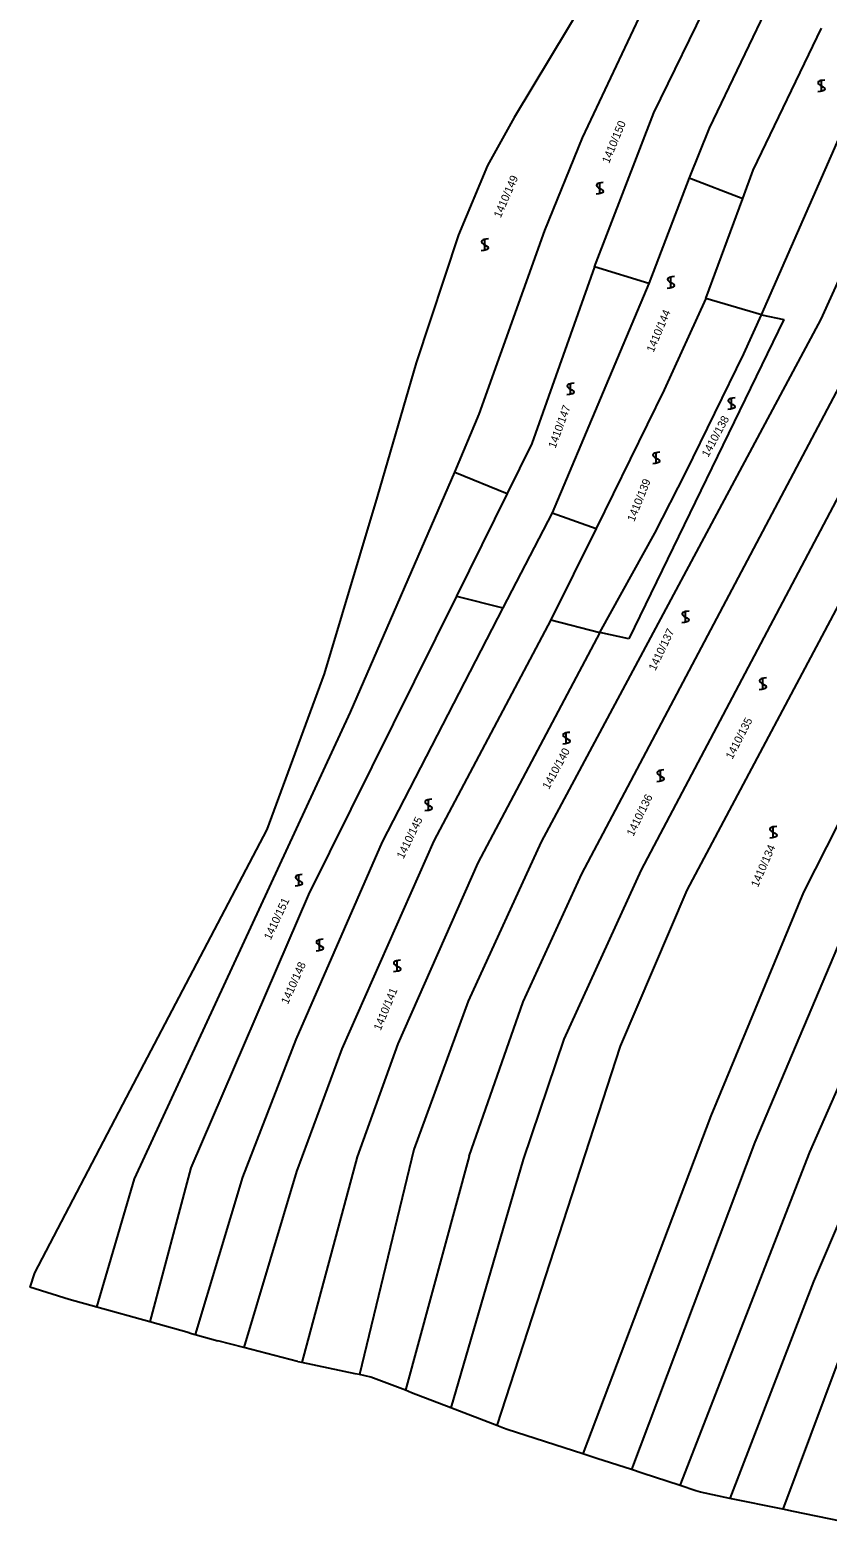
# Model space of a CAD drawing. Extents: x -580630 to -576196, y -1189024 to -1183567.
# Drawn here: x -579117.6 to -578948.4, y -1187161.3 to -1186844.5 of the extents above; entities that cross this region are included whole.
import ezdxf

# ---------------------------------------------------------------- set-up
doc = ezdxf.new("R2010")
doc.units = 0
for name, color, linetype in [('Vrstva 13', 7, 'Continuous'), ('Vrstva 18', 7, 'Continuous'), ('Vrstva 25', 7, 'Continuous'), ('Vrstva 6', 7, 'Continuous')]:
    doc.layers.add(name, color=color, linetype=linetype)

msp = doc.modelspace()

# ---------------------------------------------------------------- linework, layer by layer
at = {"layer": 'Vrstva 13'}
for p, q in [((-578999.57, -1186837.84), (-579014.8, -1186863.14)), ((-579014.8, -1186863.14), (-579020.47, -1186873.37)), ((-579020.47, -1186873.37), (-579026.64, -1186888.11)), ((-579026.64, -1186888.11), (-579035.63, -1186915.28)), ((-579035.63, -1186915.28), (-579043.9, -1186943.73)), ((-579043.9, -1186943.73), (-579055.1, -1186981.32)), ((-579055.1, -1186981.32), (-579067.33, -1187014.41)), ((-579067.33, -1187014.41), (-579097.19, -1187071.31)), ((-579097.19, -1187071.31), (-579116.64, -1187108.52)), ((-579116.64, -1187108.52), (-579117.61, -1187111.58)), ((-579109.23, -1187114.22), (-579117.61, -1187111.58)), ((-579103.42, -1187115.83), (-579109.23, -1187114.22)), ((-579092.16, -1187118.95), (-579103.42, -1187115.83)), ((-579083.76, -1187121.27), (-579092.16, -1187118.95)), ((-579083.76, -1187121.27), (-579082.53, -1187121.61)), ((-579082.53, -1187121.61), (-579077.71, -1187122.95)), ((-579072.17, -1187124.4), (-579077.71, -1187122.95)), ((-579060.76, -1187127.39), (-579072.17, -1187124.4)), ((-579060.69, -1187127.41), (-579060.76, -1187127.39)), ((-579059.87, -1187127.58), (-579060.69, -1187127.41)), ((-579048.57, -1187129.95), (-579059.87, -1187127.58)), ((-579047.64, -1187130.15), (-579048.57, -1187129.95)), ((-579045.2, -1187130.66), (-579047.64, -1187130.15)), ((-579037.89, -1187133.48), (-579045.2, -1187130.66)), ((-579036.59, -1187133.98), (-579037.89, -1187133.48)), ((-579028.28, -1187137.18), (-579036.59, -1187133.98)), ((-579018.49, -1187140.95), (-579028.28, -1187137.18)), ((-579017.04, -1187141.51), (-579018.49, -1187140.95)), ((-579016.29, -1187141.8), (-579017.04, -1187141.51)), ((-579000.21, -1187147), (-579016.29, -1187141.8)), ((-578997.23, -1187147.96), (-579000.21, -1187147)), ((-578989.87, -1187150.33), (-578997.23, -1187147.96)), ((-578987.64, -1187151.05), (-578989.87, -1187150.33)), ((-578979.56, -1187153.72), (-578987.64, -1187151.05)), ((-578976.27, -1187154.8), (-578979.56, -1187153.72)), ((-578975.26, -1187155.13), (-578976.27, -1187154.8)), ((-578969.01, -1187156.42), (-578975.26, -1187155.13)), ((-578957.79, -1187158.73), (-578969.01, -1187156.42)), ((-578955.52, -1187159.2), (-578957.79, -1187158.73)), ((-578945.5, -1187161.27), (-578955.52, -1187159.2))]:
    msp.add_line(p, q, dxfattribs=at)
at = {"layer": 'Vrstva 25'}
for points in [[(-578948.84, -1186855.22), (-578949.35, -1186855.28), (-578949.7, -1186855.33), (-578949.94, -1186855.41), (-578950.12, -1186855.52), (-578950.24, -1186855.61), (-578950.29, -1186855.78), (-578950.24, -1186856.01), (-578949.85, -1186856.33), (-578949.29, -1186856.64), (-578948.94, -1186856.91), (-578948.87, -1186857.11), (-578948.94, -1186857.31), (-578949.1, -1186857.44), (-578949.29, -1186857.51), (-578949.82, -1186857.64), (-578950.34, -1186857.71)], [(-578949.59, -1186857.72), (-578949.59, -1186856.45), (-578949.59, -1186855.22)], [(-578995.88, -1186876.98), (-578996.39, -1186877.04), (-578996.74, -1186877.09), (-578996.98, -1186877.17), (-578997.16, -1186877.28), (-578997.28, -1186877.37), (-578997.33, -1186877.54), (-578997.28, -1186877.77), (-578996.89, -1186878.09), (-578996.33, -1186878.4), (-578995.98, -1186878.67), (-578995.91, -1186878.87), (-578995.98, -1186879.07), (-578996.14, -1186879.2), (-578996.33, -1186879.27), (-578996.86, -1186879.4), (-578997.38, -1186879.47)], [(-578996.63, -1186879.48), (-578996.63, -1186878.21), (-578996.63, -1186876.98)], [(-579020.28, -1186888.97), (-579020.79, -1186889.03), (-579021.14, -1186889.08), (-579021.38, -1186889.16), (-579021.56, -1186889.27), (-579021.68, -1186889.36), (-579021.73, -1186889.53), (-579021.68, -1186889.76), (-579021.29, -1186890.08), (-579020.73, -1186890.39), (-579020.38, -1186890.66), (-579020.31, -1186890.86), (-579020.38, -1186891.06), (-579020.54, -1186891.19), (-579020.73, -1186891.26), (-579021.26, -1186891.39), (-579021.78, -1186891.46)], [(-579021.03, -1186891.47), (-579021.03, -1186890.2), (-579021.03, -1186888.97)], [(-578980.79, -1186896.96), (-578981.3, -1186897.02), (-578981.65, -1186897.07), (-578981.89, -1186897.15), (-578982.07, -1186897.26), (-578982.19, -1186897.35), (-578982.24, -1186897.52), (-578982.19, -1186897.75), (-578981.8, -1186898.07), (-578981.24, -1186898.38), (-578980.89, -1186898.65), (-578980.82, -1186898.85), (-578980.89, -1186899.05), (-578981.05, -1186899.18), (-578981.24, -1186899.25), (-578981.77, -1186899.38), (-578982.29, -1186899.45)], [(-578981.54, -1186899.46), (-578981.54, -1186898.19), (-578981.54, -1186896.96)], [(-579002.09, -1186919.6), (-579002.6, -1186919.66), (-579002.95, -1186919.71), (-579003.19, -1186919.79), (-579003.37, -1186919.9), (-579003.49, -1186919.99), (-579003.54, -1186920.16), (-579003.49, -1186920.39), (-579003.1, -1186920.71), (-579002.54, -1186921.02), (-579002.19, -1186921.29), (-579002.12, -1186921.49), (-579002.19, -1186921.69), (-579002.35, -1186921.82), (-579002.54, -1186921.89), (-579003.07, -1186922.02), (-579003.59, -1186922.09)], [(-579002.84, -1186922.1), (-579002.84, -1186920.83), (-579002.84, -1186919.6)], [(-578967.92, -1186922.71), (-578968.43, -1186922.77), (-578968.78, -1186922.82), (-578969.02, -1186922.9), (-578969.2, -1186923.01), (-578969.32, -1186923.1), (-578969.37, -1186923.27), (-578969.32, -1186923.5), (-578968.93, -1186923.82), (-578968.37, -1186924.13), (-578968.02, -1186924.4), (-578967.95, -1186924.6), (-578968.02, -1186924.8), (-578968.18, -1186924.93), (-578968.37, -1186925), (-578968.9, -1186925.13), (-578969.42, -1186925.2)], [(-578968.67, -1186925.21), (-578968.67, -1186923.94), (-578968.67, -1186922.71)], [(-578983.9, -1186934.25), (-578984.41, -1186934.31), (-578984.76, -1186934.36), (-578985, -1186934.44), (-578985.18, -1186934.55), (-578985.3, -1186934.64), (-578985.35, -1186934.81), (-578985.3, -1186935.04), (-578984.91, -1186935.36), (-578984.35, -1186935.67), (-578984, -1186935.94), (-578983.93, -1186936.14), (-578984, -1186936.34), (-578984.16, -1186936.47), (-578984.35, -1186936.54), (-578984.88, -1186936.67), (-578985.4, -1186936.74)], [(-578984.65, -1186936.75), (-578984.65, -1186935.48), (-578984.65, -1186934.25)], [(-578977.68, -1186968), (-578978.19, -1186968.06), (-578978.54, -1186968.11), (-578978.78, -1186968.19), (-578978.96, -1186968.3), (-578979.08, -1186968.39), (-578979.13, -1186968.56), (-578979.08, -1186968.79), (-578978.69, -1186969.11), (-578978.13, -1186969.42), (-578977.78, -1186969.69), (-578977.71, -1186969.89), (-578977.78, -1186970.09), (-578977.94, -1186970.22), (-578978.13, -1186970.29), (-578978.66, -1186970.42), (-578979.18, -1186970.49)], [(-578978.43, -1186970.5), (-578978.43, -1186969.23), (-578978.43, -1186968)], [(-578961.27, -1186982.2), (-578961.78, -1186982.26), (-578962.13, -1186982.31), (-578962.37, -1186982.39), (-578962.55, -1186982.5), (-578962.67, -1186982.59), (-578962.72, -1186982.76), (-578962.67, -1186982.99), (-578962.28, -1186983.31), (-578961.72, -1186983.62), (-578961.37, -1186983.89), (-578961.3, -1186984.09), (-578961.37, -1186984.29), (-578961.53, -1186984.42), (-578961.72, -1186984.49), (-578962.25, -1186984.62), (-578962.77, -1186984.69)], [(-578962.02, -1186984.7), (-578962.02, -1186983.43), (-578962.02, -1186982.2)], [(-579002.98, -1186993.75), (-579003.49, -1186993.81), (-579003.84, -1186993.86), (-579004.08, -1186993.94), (-579004.26, -1186994.05), (-579004.38, -1186994.14), (-579004.43, -1186994.31), (-579004.38, -1186994.54), (-579003.99, -1186994.86), (-579003.43, -1186995.17), (-579003.08, -1186995.44), (-579003.01, -1186995.64), (-579003.08, -1186995.84), (-579003.24, -1186995.97), (-579003.43, -1186996.04), (-579003.96, -1186996.17), (-579004.48, -1186996.24)], [(-579003.73, -1186996.25), (-579003.73, -1186994.98), (-579003.73, -1186993.75)], [(-578983.01, -1187001.74), (-578983.52, -1187001.8), (-578983.87, -1187001.85), (-578984.11, -1187001.93), (-578984.29, -1187002.04), (-578984.41, -1187002.13), (-578984.46, -1187002.3), (-578984.41, -1187002.53), (-578984.02, -1187002.85), (-578983.46, -1187003.16), (-578983.11, -1187003.43), (-578983.04, -1187003.63), (-578983.11, -1187003.83), (-578983.27, -1187003.96), (-578983.46, -1187004.03), (-578983.99, -1187004.16), (-578984.51, -1187004.23)], [(-578983.76, -1187004.24), (-578983.76, -1187002.97), (-578983.76, -1187001.74)], [(-579032.27, -1187007.95), (-579032.78, -1187008.01), (-579033.13, -1187008.06), (-579033.37, -1187008.14), (-579033.55, -1187008.25), (-579033.67, -1187008.34), (-579033.72, -1187008.51), (-579033.67, -1187008.74), (-579033.28, -1187009.06), (-579032.72, -1187009.37), (-579032.37, -1187009.64), (-579032.3, -1187009.84), (-579032.37, -1187010.04), (-579032.53, -1187010.17), (-579032.72, -1187010.24), (-579033.25, -1187010.37), (-579033.77, -1187010.44)], [(-579033.02, -1187010.45), (-579033.02, -1187009.18), (-579033.02, -1187007.95)], [(-578959.05, -1187013.73), (-578959.56, -1187013.79), (-578959.91, -1187013.84), (-578960.15, -1187013.92), (-578960.33, -1187014.03), (-578960.45, -1187014.12), (-578960.5, -1187014.29), (-578960.45, -1187014.52), (-578960.06, -1187014.84), (-578959.5, -1187015.15), (-578959.15, -1187015.42), (-578959.08, -1187015.62), (-578959.15, -1187015.82), (-578959.31, -1187015.95), (-578959.5, -1187016.02), (-578960.03, -1187016.15), (-578960.55, -1187016.22)], [(-578959.8, -1187016.23), (-578959.8, -1187014.96), (-578959.8, -1187013.73)], [(-579059.78, -1187023.94), (-579060.29, -1187024), (-579060.64, -1187024.05), (-579060.88, -1187024.13), (-579061.06, -1187024.24), (-579061.18, -1187024.33), (-579061.23, -1187024.5), (-579061.18, -1187024.73), (-579060.79, -1187025.05), (-579060.23, -1187025.36), (-579059.88, -1187025.63), (-579059.81, -1187025.83), (-579059.88, -1187026.03), (-579060.04, -1187026.16), (-579060.23, -1187026.23), (-579060.76, -1187026.36), (-579061.28, -1187026.43)], [(-579060.53, -1187026.44), (-579060.53, -1187025.17), (-579060.53, -1187023.94)], [(-579055.34, -1187037.7), (-579055.85, -1187037.76), (-579056.2, -1187037.81), (-579056.44, -1187037.89), (-579056.62, -1187038), (-579056.74, -1187038.09), (-579056.79, -1187038.26), (-579056.74, -1187038.49), (-579056.35, -1187038.81), (-579055.79, -1187039.12), (-579055.44, -1187039.39), (-579055.37, -1187039.59), (-579055.44, -1187039.79), (-579055.6, -1187039.92), (-579055.79, -1187039.99), (-579056.32, -1187040.12), (-579056.84, -1187040.19)], [(-579056.09, -1187040.2), (-579056.09, -1187038.93), (-579056.09, -1187037.7)], [(-579038.92, -1187042.14), (-579039.43, -1187042.2), (-579039.78, -1187042.25), (-579040.02, -1187042.33), (-579040.2, -1187042.44), (-579040.32, -1187042.53), (-579040.37, -1187042.7), (-579040.32, -1187042.93), (-579039.93, -1187043.25), (-579039.37, -1187043.56), (-579039.02, -1187043.83), (-579038.95, -1187044.03), (-579039.02, -1187044.23), (-579039.18, -1187044.36), (-579039.37, -1187044.43), (-579039.9, -1187044.56), (-579040.42, -1187044.63)], [(-579039.67, -1187044.64), (-579039.67, -1187043.37), (-579039.67, -1187042.14)]]:
    msp.add_lwpolyline(points, dxfattribs=at)
at = {"layer": 'Vrstva 6'}
for p, q in [((-578985.14, -1186862.19), (-578963.45, -1186817.75)), ((-578875.7, -1186834.25), (-578978.18, -1187027.28)), ((-578958.69, -1186834.68), (-578973.44, -1186865.4)), ((-579000.29, -1186867.51), (-578987.07, -1186839.43)), ((-578964.05, -1186874.33), (-578949.6, -1186844.17)), ((-578925.2, -1186851.92), (-578949.74, -1186905.97)), ((-578962.33, -1186905.11), (-578940.96, -1186856.38)), ((-578997.74, -1186894.91), (-578985.14, -1186862.19)), ((-578973.44, -1186865.4), (-578977.63, -1186876)), ((-579008.26, -1186887.2), (-579000.29, -1186867.51)), ((-578977.63, -1186876), (-578986.2, -1186898.43)), ((-578977.63, -1186876), (-578966.28, -1186880.38)), ((-578966.28, -1186880.38), (-578964.05, -1186874.33)), ((-578974.1, -1186901.62), (-578966.28, -1186880.38)), ((-579022.21, -1186926.14), (-579008.26, -1186887.2)), ((-578997.74, -1186894.91), (-579011.06, -1186932.42)), ((-578986.2, -1186898.43), (-578997.74, -1186894.91)), ((-578986.2, -1186898.43), (-579006.77, -1186947.1)), ((-578974.1, -1186901.62), (-578982.98, -1186920.97)), ((-578962.33, -1186905.11), (-578974.1, -1186901.62)), ((-578949.74, -1186905.97), (-579009.08, -1187017.03)), ((-579000.42, -1187023.78), (-578938.51, -1186906.52)), ((-578957.55, -1186906.06), (-578990.46, -1186973.9)), ((-578966.08, -1186913.39), (-578962.33, -1186905.11)), ((-578962.33, -1186905.11), (-578957.55, -1186906.06)), ((-578978.35, -1186938.59), (-578966.08, -1186913.39)), ((-578931.17, -1186915.46), (-578987.86, -1187022.91)), ((-578982.98, -1186920.97), (-578997.4, -1186950.47)), ((-579027.37, -1186938.49), (-579022.21, -1186926.14)), ((-579011.06, -1186932.42), (-579016.27, -1186943)), ((-579049.54, -1186989.43), (-579027.37, -1186938.49)), ((-579027.37, -1186938.49), (-579016.27, -1186943)), ((-578984.96, -1186951.42), (-578978.35, -1186938.59)), ((-579016.27, -1186943), (-579027.01, -1186964.81)), ((-579006.77, -1186947.1), (-579017.22, -1186967.28)), ((-579006.77, -1186947.1), (-578997.4, -1186950.47)), ((-578997.4, -1186950.47), (-579007.05, -1186969.86)), ((-578996.59, -1186972.55), (-578984.96, -1186951.42)), ((-579027.01, -1186964.81), (-579058.44, -1187028.21)), ((-579027.01, -1186964.81), (-579017.22, -1186967.28)), ((-579017.22, -1186967.28), (-579042.8, -1187016.99)), ((-579007.05, -1186969.86), (-579031.84, -1187016.76)), ((-579007.05, -1186969.86), (-578996.59, -1186972.55)), ((-578996.59, -1186972.55), (-579022.51, -1187021.49)), ((-578990.46, -1186973.9), (-578996.59, -1186972.55)), ((-578926.31, -1186974.11), (-578953.39, -1187027.68)), ((-579095.38, -1187088.59), (-579049.54, -1186989.43)), ((-578952.07, -1187082.93), (-578922.28, -1187015.01)), ((-579042.8, -1187016.99), (-579061.13, -1187058.96)), ((-579031.84, -1187016.76), (-579051.38, -1187060.97)), ((-579009.08, -1187017.03), (-579024.54, -1187050.82)), ((-579022.51, -1187021.49), (-579039.49, -1187059.87)), ((-579012.9, -1187050.98), (-579000.42, -1187023.78)), ((-578987.86, -1187022.91), (-579004.28, -1187058.94)), ((-579058.44, -1187028.21), (-579083.41, -1187086.21)), ((-578978.18, -1187027.28), (-578992.29, -1187060.38)), ((-578953.39, -1187027.68), (-578973.07, -1187075.19)), ((-578943.03, -1187031.9), (-578963.69, -1187080.78)), ((-579024.54, -1187050.82), (-579036.09, -1187082.32)), ((-579024.39, -1187083.74), (-579012.9, -1187050.98)), ((-579061.13, -1187058.96), (-579072.46, -1187088.24)), ((-579039.49, -1187059.87), (-579048.11, -1187083.89)), ((-579004.28, -1187058.94), (-579012.9, -1187084.46)), ((-579051.38, -1187060.97), (-579061.03, -1187086.99)), ((-578992.29, -1187060.38), (-579018.49, -1187140.95)), ((-578973.07, -1187075.19), (-579000.21, -1187147)), ((-579036.09, -1187082.32), (-579047.64, -1187130.15)), ((-578963.69, -1187080.78), (-578989.87, -1187150.33)), ((-579048.11, -1187083.89), (-579059.87, -1187127.58)), ((-579024.39, -1187083.74), (-579037.89, -1187133.48)), ((-579012.9, -1187084.46), (-579028.28, -1187137.18)), ((-578979.56, -1187153.72), (-578952.07, -1187082.93)), ((-579103.42, -1187115.83), (-579095.38, -1187088.59)), ((-579083.41, -1187086.21), (-579092.16, -1187118.95)), ((-579072.46, -1187088.24), (-579082.53, -1187121.61)), ((-579061.03, -1187086.99), (-579072.17, -1187124.4)), ((-578944.72, -1187095.17), (-578951.26, -1187110.4)), ((-578951.26, -1187110.4), (-578969.01, -1187156.42)), ((-578946, -1187127.29), (-578957.79, -1187158.73))]:
    msp.add_line(p, q, dxfattribs=at)

# ---------------------------------------------------------------- texts
at = {"layer": 'Vrstva 18'}
for s, rotation, p in [('1410/150', 67.49443, (-578994.674, -1186873.06)), ('1410/149', 66.57769, (-579017.672, -1186884.624)), ('1410/144', 67.20795, (-578985.227, -1186913.174)), ('1410/147', 69.90085, (-579006.047, -1186933.553)), ('1410/138', 61.59296, (-578973.614, -1186935.448)), ('1410/139', 68.12468, (-578989.313, -1186949.132)), ('1410/137', 64.45775, (-578984.833, -1186980.788)), ('1410/135', 62.73888, (-578968.495, -1186999.605)), ('1410/140', 61.42108, (-579007.438, -1187006.001)), ('1410/136', 64.05668, (-578989.5, -1187015.94)), ('1410/145', 64.17127, (-579038.314, -1187020.748)), ('1410/134', 66.63499, (-578963.063, -1187026.776)), ('1410/151', 64.85882, (-579066.487, -1187037.966)), ('1410/148', 65.89015, (-579062.83, -1187051.631)), ('1410/141', 67.49443, (-579043.153, -1187057.211))]:
    msp.add_text(s, height=1.7, rotation=rotation, dxfattribs=at).set_placement(p)

doc.saveas('drawing.dxf')
